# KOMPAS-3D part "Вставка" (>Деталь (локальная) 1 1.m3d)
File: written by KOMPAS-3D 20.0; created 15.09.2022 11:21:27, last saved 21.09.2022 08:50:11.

Document properties: Полное имя файла: C:\Users\yakovlev_sv\AppData\Local\Temp\KOMPAS-3D\ktf7-07b3-e7fe-b595\_Деталь (локальная) 1 1.m3d

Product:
- Part/product: Вставка
    Материал: Сталь 45  ГОСТ 1050-2013 (density 7810 kg/m3)
    Масса: 5247.53

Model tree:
1. Эскиз:1  (with: Смещенная плоскость:1)
2. Обечайка:1
     Расстояние 1 = 1655.66; Толщина листового тела = 110
3. Сгиб(1) - Обечайка:1
     Радиус сгиба = 500; Коэффициент = 0.4; Величина сгиба = 10; Зазор = 0.01
4. Смещенная плоскость:1
5. Касательная плоскость:1  (with: Обечайка:1)
6. Фаска:1  (with: Обечайка:1)
     Угол = 45; Длина 1 = 90; Длина 2 = 90
7. Развертка  (labels: Сталь 45  ГОСТ 1050-2013)

Expressions: 900+100
Referenced files in D:\YAKOVLEV\ПРОЕКТЫ\ДЦ-2. ДП-7 Газопровод Окожушивание\ПРОБА Соединение труб. Окожушивание\ПРОБА 2\: Соединение труб -2.a3d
